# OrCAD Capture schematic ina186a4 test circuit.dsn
size A
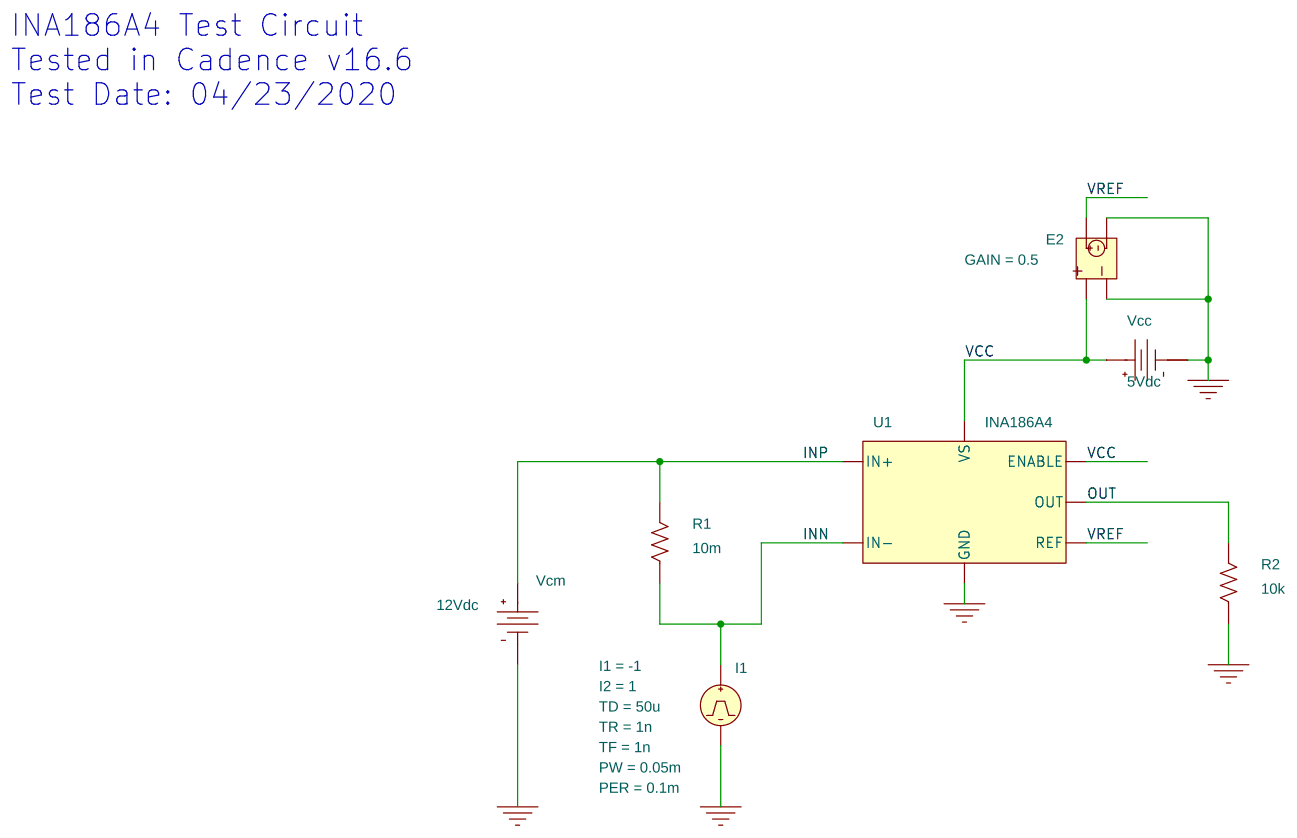
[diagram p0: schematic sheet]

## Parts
E2  E
I1  IPULSE
R1  10m  [AX/RC05]
R2  10k  [AX/RC05]
U1  INA186A4
Vcc  VDC
Vcm  VDC

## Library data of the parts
E2 = E: GAIN: 0.5
I1 = IPULSE: I1: -1; I2: 1; PER: 0.1m; PW: 0.05m; TD: 50u; TF: 1n; TR: 1n
R1 R2 = R
U1 = INA186A4
Vcc = VDC: DC: 5Vdc
Vcm = VDC: DC: 12Vdc

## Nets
VCC: E2.1 U1.ENABLE U1.VS Vcc.0(+)
0: E2.2 E2.4 I1.2(-) R2.1 U1.GND Vcc.1(-) Vcm.1(-)
INN: I1.1(+) R1.1 U1.IN-
INP: R1.2 U1.IN+ Vcm.0(+)
OUT: R2.2 U1.OUT
VREF: E2.3 U1.REF

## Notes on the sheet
- INA186A4 Test Circuit
  Tested in Cadence v16.6
  Test Date: 04/23/2020
